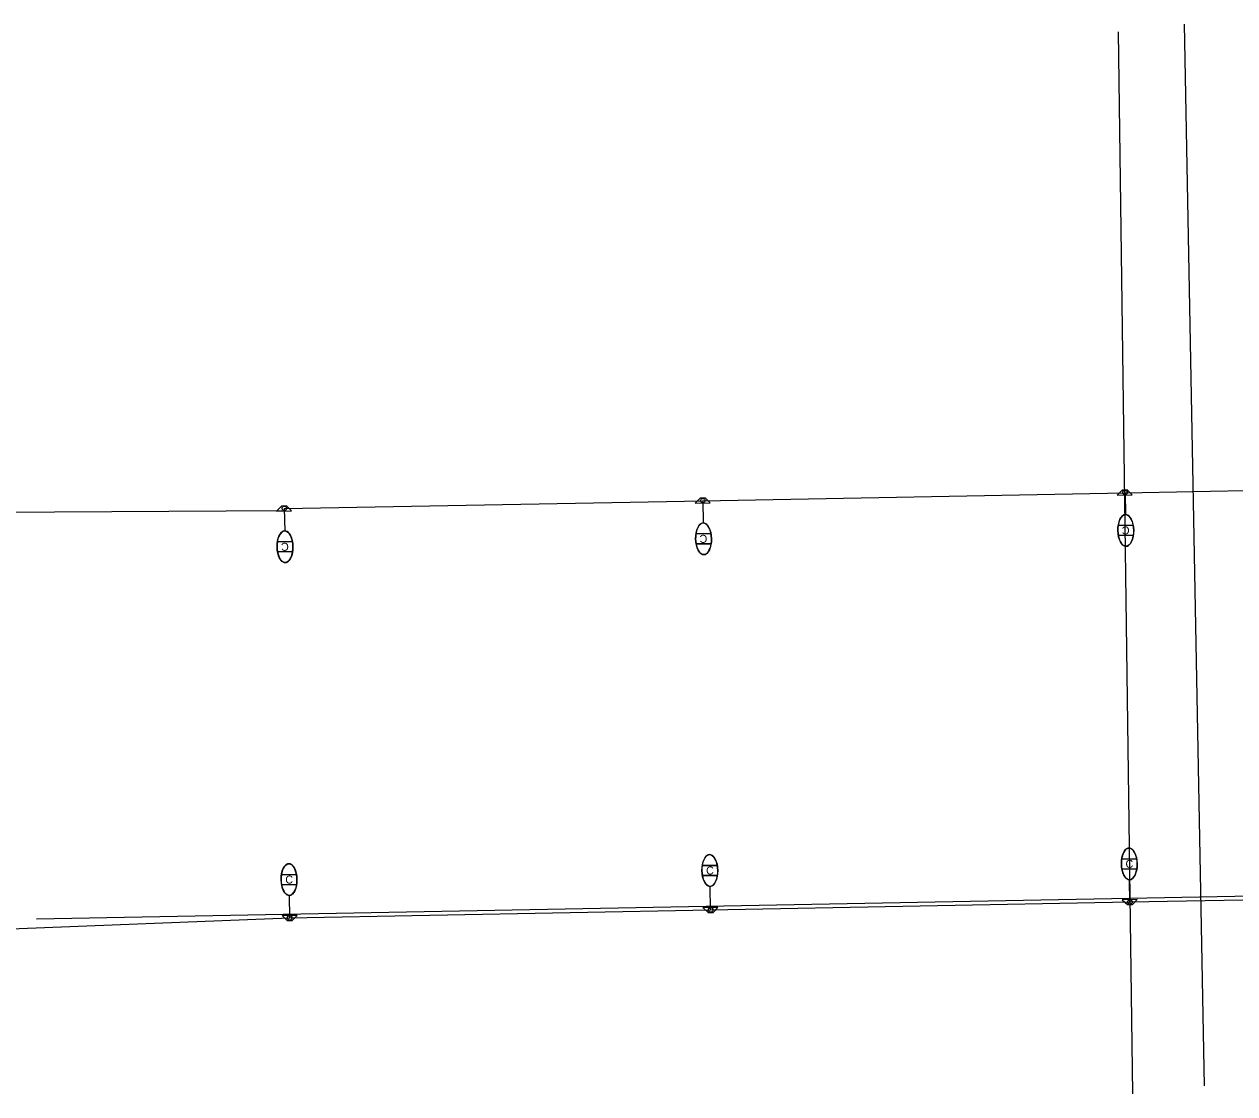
# Model space of a CAD drawing. Extents: x 915723 to 927758, y 636394 to 638609.
# Drawn here: x 921825 to 922430, y 636836 to 637370 of the extents above; entities that cross this region are included whole.
import ezdxf

# ---------------------------------------------------------------- set-up
doc = ezdxf.new("R2010")
doc.units = 0
for name, color, linetype in [('ConduitBM', 7, 'Continuous'), ('DrShaftConc', 7, 'Continuous'), ('Masonry_h', 7, 'Continuous'), ('Miscellaneous2', 7, 'Continuous'), ('PoleLight', 7, 'Continuous'), ('TextStructuresLabel', 7, 'Continuous')]:
    doc.layers.add(name, color=color, linetype=linetype)

msp = doc.modelspace()

# ---------------------------------------------------------------- linework, layer by layer
at = {"layer": 'ConduitBM'}
for p, q in [((922375.31, 637135.96), (922584.95, 637140.09)), ((922164.29, 637131.94), (922375.31, 637135.96)), ((921955.13, 637128.01), (922164.29, 637131.94)), ((922377.73, 636931.52), (922587.7, 636935.51)), ((922168.17, 636927.53), (922377.73, 636931.52)), ((921814.1, 636917.87), (921957.87, 636923.54)), ((921957.8, 636923.54), (922168.17, 636927.53))]:
    msp.add_line(p, q, dxfattribs=at)
at = {"layer": 'DrShaftConc'}
for p, q in [((922404.81, 637370.03), (922414.88, 636839.56)), ((921954.64, 637126.86), (921809.69, 637125.99))]:
    msp.add_line(p, q, dxfattribs=at)
msp.add_lwpolyline([(921831.32, 636923.01), (923099.42, 636947.08), (923099.42, 636947.08), (923194.81, 636948.49), (923290.21, 636949.1), (923385.61, 636948.91), (923481.01, 636947.93), (923576.4, 636946.14), (923671.76, 636943.55), (923767.11, 636940.16), (923862.42, 636935.97), (923957.69, 636930.98), (924052.92, 636925.2), (924148.09, 636918.61), (924243.21, 636911.23)], dxfattribs=at)
at = {"layer": 'Masonry_h'}
msp.add_line((922371.91, 637366.19), (922379.01, 636835.67), dxfattribs=at)
at = {"layer": 'Miscellaneous2'}
for p, q in [((922379.38, 637119.7), (922371.86, 637119.56)), ((922371.86, 637119.56), (922371.86, 637119.56)), ((921959.2, 637111.54), (921951.69, 637111.39)), ((921951.69, 637111.39), (921951.69, 637111.39)), ((922168.36, 637115.51), (922160.84, 637115.37)), ((922160.84, 637115.37), (922160.84, 637115.37)), ((922160.94, 637110.37), (922168.45, 637110.51)), ((922160.94, 637110.37), (922160.94, 637110.37)), ((922371.96, 637114.56), (922379.47, 637114.7)), ((922371.96, 637114.56), (922371.96, 637114.56)), ((921951.78, 637106.4), (921959.3, 637106.54)), ((921951.78, 637106.4), (921951.78, 637106.4)), ((922381.11, 636953.1), (922373.6, 636952.96)), ((922381.11, 636953.1), (922381.11, 636953.1)), ((922171.5, 636949.79), (922163.99, 636949.64)), ((922171.5, 636949.79), (922171.5, 636949.79)), ((922373.7, 636947.96), (922381.21, 636948.1)), ((922381.21, 636948.1), (922381.21, 636948.1)), ((921961.22, 636945.26), (921953.71, 636945.12)), ((921953.8, 636940.12), (921961.32, 636940.26)), ((921961.22, 636945.26), (921961.22, 636945.26)), ((921961.32, 636940.26), (921961.32, 636940.26)), ((922164.08, 636944.65), (922171.6, 636944.79)), ((922171.6, 636944.79), (922171.6, 636944.79))]:
    msp.add_line(p, q, dxfattribs=at)
for centre, major_axis, start_param, end_param in [((922375.67, 637117.13), (-0.15, 7.92), 1.249648, 1.891946), ((922375.67, 637117.13), (-0.15, 7.92), 4.391271, 5.033538), ((921955.49, 637108.97), (-0.15, 7.92), 1.249648, 1.891946), ((921955.49, 637108.97), (-0.15, 7.92), 4.391271, 5.033538), ((922164.65, 637112.94), (-0.15, 7.92), 1.249648, 1.891946), ((922164.65, 637112.94), (-0.15, 7.92), 4.391271, 5.033538), ((922164.65, 637112.94), (-0.15, 7.92), 4.391241, 4.391271), ((922375.67, 637117.13), (-0.15, 7.92), 4.391241, 4.391271), ((921955.49, 637108.97), (-0.15, 7.92), 4.391241, 4.391271), ((922377.4, 636950.53), (0.15, -7.92), 4.391271, 5.033538), ((922377.4, 636950.53), (0.15, -7.92), 4.391241, 4.391271), ((922377.4, 636950.53), (0.15, -7.92), 1.249648, 1.891946), ((922167.79, 636947.22), (0.15, -7.92), 4.391271, 5.033538), ((922167.79, 636947.22), (0.15, -7.92), 4.391241, 4.391271), ((922167.79, 636947.22), (0.15, -7.92), 1.249648, 1.891946), ((921957.51, 636942.69), (0.15, -7.92), 4.391271, 5.033538), ((921957.51, 636942.69), (0.15, -7.92), 4.391241, 4.391271), ((921957.51, 636942.69), (0.15, -7.92), 1.249648, 1.891946)]:
    msp.add_ellipse(centre, major_axis=major_axis, ratio=0.5, start_param=start_param, end_param=end_param, dxfattribs=at)
at = {"layer": 'PoleLight'}
for p, q in [((922375.31, 637135.96), (922375.52, 637125.05)), ((921955.13, 637128.15), (921955.34, 637116.89)), ((922164.28, 637132), (922164.5, 637120.86)), ((922371.86, 637119.56), (922379.38, 637119.7)), ((921951.69, 637111.39), (921959.2, 637111.54)), ((922160.84, 637115.37), (922168.36, 637115.51)), ((922168.45, 637110.51), (922160.94, 637110.37)), ((922379.47, 637114.7), (922371.96, 637114.56)), ((921959.3, 637106.54), (921951.78, 637106.4)), ((922373.6, 636952.96), (922381.11, 636953.1)), ((922163.99, 636949.64), (922171.5, 636949.79)), ((922381.21, 636948.1), (922373.7, 636947.96)), ((921953.71, 636945.12), (921961.22, 636945.26)), ((921961.32, 636940.26), (921953.8, 636940.12)), ((922171.6, 636944.79), (922164.08, 636944.65)), ((922377.77, 636931.45), (922377.55, 636942.61)), ((921957.87, 636923.54), (921957.66, 636934.77)), ((922168.17, 636927.53), (922167.94, 636939.3))]:
    msp.add_line(p, q, dxfattribs=at)
for points in [[(922376.36, 637137.36), (922373.86, 637137.31), (922371.4, 637134.77), (922378.9, 637134.91)], [(921956.21, 637129.39), (921953.71, 637129.33), (921951.26, 637126.79), (921958.76, 637126.94)], [(922165.44, 637133.36), (922162.94, 637133.31), (922160.49, 637130.77), (922167.98, 637130.91)], [(922166.9, 636926.21), (922169.4, 636926.26), (922171.85, 636928.81), (922164.35, 636928.66)], [(922376.46, 636930.18), (922378.96, 636930.23), (922381.42, 636932.77), (922373.92, 636932.63)], [(921956.54, 636922.22), (921959.04, 636922.27), (921961.49, 636924.81), (921953.99, 636924.67)]]:
    msp.add_lwpolyline(points, close=True, dxfattribs=at)
for centre in [(922375.29, 637136.04), (921955.18, 637128.15), (922164.28, 637132), (922168.17, 636927.53), (922377.73, 636931.5), (921957.81, 636923.54)]:
    msp.add_circle(centre, 1.14, dxfattribs=at)
for centre, major_axis in [((922375.67, 637117.13), (-0.15, 7.92)), ((921955.49, 637108.97), (-0.15, 7.92)), ((922164.65, 637112.94), (-0.15, 7.92)), ((922377.4, 636950.53), (0.15, -7.92)), ((922167.79, 636947.22), (0.15, -7.92)), ((921957.51, 636942.69), (0.15, -7.92))]:
    msp.add_ellipse(centre, major_axis=major_axis, ratio=0.5, dxfattribs=at)
for centre, major_axis, start_param, end_param in [((922375.67, 637117.13), (-0.15, 7.92), 0.847605, 1.249648), ((922375.67, 637117.13), (-0.15, 7.92), 0, 0.847605), ((922375.67, 637117.13), (-0.15, 7.92), 5.033538, 6.283185), ((921955.49, 637108.97), (-0.15, 7.92), 0, 0.847605), ((921955.49, 637108.97), (-0.15, 7.92), 5.033538, 6.283185), ((922164.65, 637112.94), (-0.15, 7.92), 0.847605, 1.249648), ((922164.65, 637112.94), (-0.15, 7.92), 0, 0.847605), ((922164.65, 637112.94), (-0.15, 7.92), 5.033538, 6.283185), ((921955.49, 637108.97), (-0.15, 7.92), 0.847605, 1.249648), ((922164.65, 637112.94), (-0.15, 7.92), 1.891945, 4.391241), ((922375.67, 637117.13), (-0.15, 7.92), 1.891945, 4.391241), ((921955.49, 637108.97), (-0.15, 7.92), 1.891945, 4.391241), ((922377.4, 636950.53), (0.15, -7.92), 1.891945, 4.391241), ((922167.79, 636947.22), (0.15, -7.92), 1.891945, 4.391241), ((921957.51, 636942.69), (0.15, -7.92), 1.891945, 4.391241), ((922377.4, 636950.53), (0.15, -7.92), 5.033538, 6.283185), ((922377.4, 636950.53), (0.15, -7.92), 0.847605, 1.249648), ((921957.51, 636942.69), (0.15, -7.92), 0.847605, 1.249648), ((922167.79, 636947.22), (0.15, -7.92), 5.033538, 6.283185), ((922167.79, 636947.22), (0.15, -7.92), 0, 0.847605), ((922167.79, 636947.22), (0.15, -7.92), 0.847605, 1.249648), ((922377.4, 636950.53), (0.15, -7.92), 0, 0.847605), ((921957.51, 636942.69), (0.15, -7.92), 5.033538, 6.283185), ((921957.51, 636942.69), (0.15, -7.92), 0, 0.847605)]:
    msp.add_ellipse(centre, major_axis=major_axis, ratio=0.5, start_param=start_param, end_param=end_param, dxfattribs=at)

# ---------------------------------------------------------------- texts
at = {"layer": 'TextStructuresLabel'}
for rotation, p in [(181.08772, (922377.5, 637119.17)), (181.08772, (921957.33, 637111)), (181.08772, (922166.48, 637114.97)), (1.08772, (922375.57, 636948.49)), (1.08772, (922165.96, 636945.18)), (1.08772, (921955.68, 636940.65))]:
    msp.add_text('C', height=4, rotation=rotation, dxfattribs=at).set_placement(p)

doc.saveas('drawing.dxf')
